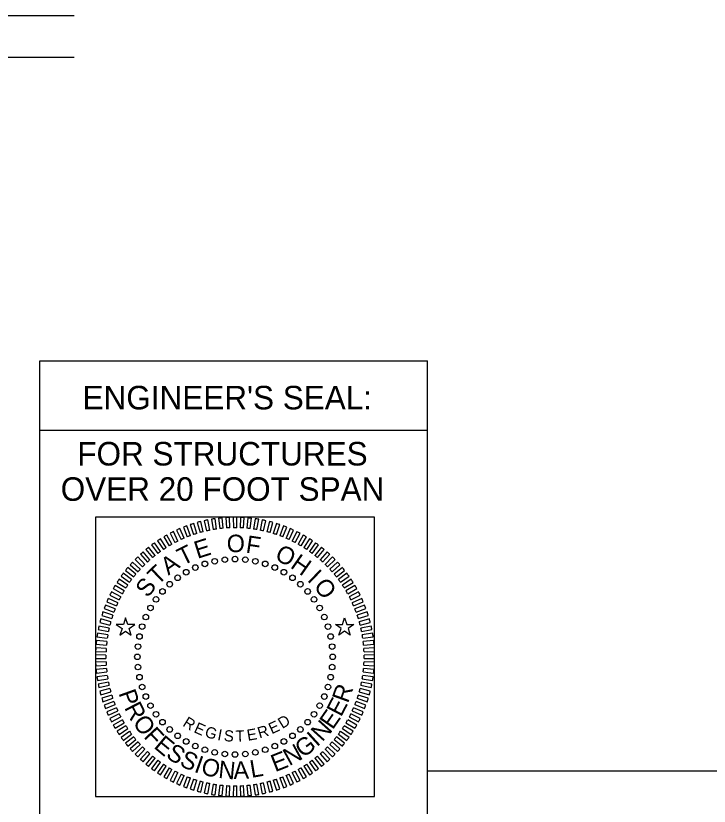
# Model space of a CAD drawing. Extents: x 2080852 to 2433556, y 1080825 to 1306626.
# Drawn here: x 2165094 to 2217967, y 1134021 to 1194273 of the extents above; entities that cross this region are included whole.
import ezdxf

# ---------------------------------------------------------------- set-up
doc = ezdxf.new("R2010")
doc.units = 0
for name, color, linetype in [('Default', 7, 'Continuous'), ('PM_P_Lane_Line', 7, 'Continuous'), ('SC_Scratch1', 7, 'Continuous')]:
    doc.layers.add(name, color=color, linetype=linetype)

msp = doc.modelspace()

# ---------------------------------------------------------------- linework, layer by layer
at = {"layer": 'PM_P_Lane_Line'}
for p, q in [((2169556, 1194273), (2156356, 1194273)), ((2169556, 1191105), (2156356, 1191105)), ((2166916, 1086105), (2166916, 1167965)), ((2166916, 1167965), (2196484, 1167965)), ((2196484, 1086105), (2196484, 1167965)), ((2166916, 1162685), (2196484, 1162685)), ((2178924, 1155648), (2179141, 1154880)), ((2179390, 1154947), (2179193, 1155721)), ((2179464, 1155786), (2179640, 1155007)), ((2179892, 1155061), (2179737, 1155843)), ((2180010, 1155894), (2180146, 1155108)), ((2180400, 1155148), (2180286, 1155938)), ((2180562, 1155974), (2180656, 1155182)), ((2180912, 1155209), (2180839, 1156003)), ((2181116, 1156025), (2181169, 1155229)), ((2181426, 1155242), (2181395, 1156040)), ((2181673, 1156047), (2181684, 1155249)), ((2181941, 1155249), (2181952, 1156047)), ((2182230, 1156040), (2182199, 1155242)), ((2182456, 1155229), (2182508, 1156025)), ((2182786, 1156003), (2182713, 1155209)), ((2182969, 1155182), (2183063, 1155974)), ((2183339, 1155938), (2183225, 1155148)), ((2183479, 1155108), (2183614, 1155894)), ((2183888, 1155843), (2183732, 1155061)), ((2183985, 1155007), (2184161, 1155786)), ((2184431, 1155721), (2184235, 1154947)), ((2184484, 1154880), (2184701, 1155648)), ((2177358, 1155071), (2177692, 1154346)), ((2177927, 1154451), (2177612, 1155184)), ((2177870, 1155290), (2178165, 1154549)), ((2178406, 1154642), (2178130, 1155390)), ((2178392, 1155483), (2178649, 1154728)), ((2178894, 1154807), (2178657, 1155569)), ((2184968, 1155569), (2184731, 1154807)), ((2184976, 1154728), (2185233, 1155483)), ((2185495, 1155390), (2185219, 1154642)), ((2185459, 1154549), (2185755, 1155290)), ((2186013, 1155184), (2185698, 1154451)), ((2185933, 1154346), (2186267, 1155071)), ((2176372, 1154552), (2176780, 1153866)), ((2177003, 1153995), (2176613, 1154691)), ((2176858, 1154824), (2177230, 1154118)), ((2177459, 1154235), (2177106, 1154951)), ((2186518, 1154951), (2186165, 1154235)), ((2186395, 1154118), (2186767, 1154824)), ((2187011, 1154691), (2186621, 1153995)), ((2186845, 1153866), (2187253, 1154552)), ((2175446, 1153933), (2175924, 1153294)), ((2176132, 1153445), (2175671, 1154097)), ((2175901, 1154255), (2176344, 1153591)), ((2176560, 1153732), (2176135, 1154406)), ((2187490, 1154406), (2187064, 1153732)), ((2187280, 1153591), (2187724, 1154255)), ((2187953, 1154097), (2187493, 1153445)), ((2187701, 1153294), (2188179, 1153933)), ((2174590, 1153221), (2175131, 1152635)), ((2175323, 1152807), (2174797, 1153407)), ((2175009, 1153588), (2175519, 1152975)), ((2175719, 1153137), (2175225, 1153764)), ((2188400, 1153764), (2187906, 1153137)), ((2188106, 1152975), (2188616, 1153588)), ((2188828, 1153407), (2188302, 1152807)), ((2188493, 1152635), (2189035, 1153221)), ((2174585, 1152089), (2173999, 1152630)), ((2174191, 1152832), (2174762, 1152275)), ((2174945, 1152458), (2174388, 1153029)), ((2189237, 1153029), (2188680, 1152458)), ((2188862, 1152275), (2189434, 1152832)), ((2189626, 1152630), (2189040, 1152089)), ((2174245, 1151701), (2173632, 1152211)), ((2173813, 1152423), (2174413, 1151897)), ((2189212, 1151897), (2189812, 1152423)), ((2189993, 1152211), (2189379, 1151701)), ((2173123, 1151549), (2173775, 1151088)), ((2173926, 1151297), (2173287, 1151774)), ((2173456, 1151995), (2174083, 1151501)), ((2189542, 1151501), (2190168, 1151995)), ((2190338, 1151774), (2189698, 1151297)), ((2189850, 1151088), (2190502, 1151549)), ((2173354, 1150440), (2172668, 1150848)), ((2172814, 1151085), (2173489, 1150660)), ((2173629, 1150876), (2172965, 1151319)), ((2190659, 1151319), (2189996, 1150876)), ((2190136, 1150660), (2190811, 1151085)), ((2190957, 1150848), (2190271, 1150440)), ((2173102, 1149990), (2172396, 1150362)), ((2172529, 1150607), (2173225, 1150217)), ((2190400, 1150217), (2191096, 1150607)), ((2191229, 1150362), (2190523, 1149990)), ((2172036, 1149608), (2172769, 1149293)), ((2172874, 1149528), (2172150, 1149862)), ((2172269, 1150114), (2172985, 1149761)), ((2190640, 1149761), (2191355, 1150114)), ((2191475, 1149862), (2190750, 1149528)), ((2190855, 1149293), (2191588, 1149608)), ((2171830, 1149090), (2172579, 1148814)), ((2172671, 1149055), (2171930, 1149351)), ((2191695, 1149351), (2190954, 1149055)), ((2191046, 1148814), (2191795, 1149090)), ((2171651, 1148563), (2172413, 1148326)), ((2172493, 1148571), (2171737, 1148828)), ((2191888, 1148828), (2191132, 1148571)), ((2191212, 1148326), (2191974, 1148563)), ((2171500, 1148027), (2172273, 1147830)), ((2172340, 1148079), (2171572, 1148296)), ((2192053, 1148296), (2191285, 1148079)), ((2191352, 1147830), (2192125, 1148027)), ((2172112, 1147074), (2171326, 1147210)), ((2171377, 1147483), (2172159, 1147328)), ((2172213, 1147580), (2171435, 1147756)), ((2192190, 1147756), (2191412, 1147580)), ((2191465, 1147328), (2192248, 1147483)), ((2192299, 1147210), (2191512, 1147074)), ((2172038, 1146565), (2171246, 1146658)), ((2171282, 1146934), (2172072, 1146820)), ((2191553, 1146820), (2192342, 1146934)), ((2192379, 1146658), (2191586, 1146565)), ((2171991, 1146051), (2171195, 1146104)), ((2171217, 1146381), (2172011, 1146308)), ((2191613, 1146308), (2192408, 1146381)), ((2192430, 1146104), (2191633, 1146051)), ((2171971, 1145537), (2171173, 1145547)), ((2171180, 1145825), (2171978, 1145794)), ((2191647, 1145794), (2192444, 1145825)), ((2192452, 1145547), (2191654, 1145537)), ((2171173, 1145268), (2171971, 1145279)), ((2171978, 1145021), (2171180, 1144990)), ((2192444, 1144990), (2191647, 1145021)), ((2191654, 1145279), (2192452, 1145268)), ((2171195, 1144712), (2171991, 1144764)), ((2172011, 1144507), (2171217, 1144434)), ((2171246, 1144157), (2172038, 1144251)), ((2191586, 1144251), (2192379, 1144157)), ((2192408, 1144434), (2191613, 1144507)), ((2191633, 1144764), (2192430, 1144712)), ((2172072, 1143995), (2171282, 1143881)), ((2171326, 1143606), (2172112, 1143741)), ((2191512, 1143741), (2192299, 1143606)), ((2192342, 1143881), (2191553, 1143995)), ((2172159, 1143488), (2171377, 1143332)), ((2171435, 1143059), (2172213, 1143236)), ((2172273, 1142985), (2171500, 1142789)), ((2192125, 1142789), (2191352, 1142985)), ((2191412, 1143236), (2192190, 1143059)), ((2192248, 1143332), (2191465, 1143488)), ((2171572, 1142520), (2172340, 1142736)), ((2172413, 1142489), (2171651, 1142252)), ((2191974, 1142252), (2191212, 1142489)), ((2191285, 1142736), (2192053, 1142520)), ((2171737, 1141988), (2172493, 1142244)), ((2172579, 1142001), (2171830, 1141725)), ((2191795, 1141725), (2191046, 1142001)), ((2191132, 1142244), (2191888, 1141988)), ((2171930, 1141465), (2172671, 1141761)), ((2172769, 1141523), (2172036, 1141208)), ((2172150, 1140953), (2172874, 1141287)), ((2190750, 1141287), (2191475, 1140953)), ((2191588, 1141208), (2190855, 1141523)), ((2190954, 1141761), (2191695, 1141465)), ((2172985, 1141055), (2172269, 1140702)), ((2172396, 1140453), (2173102, 1140825)), ((2173225, 1140599), (2172529, 1140209)), ((2191096, 1140209), (2190400, 1140599)), ((2190523, 1140825), (2191229, 1140453)), ((2191355, 1140702), (2190640, 1141055)), ((2172668, 1139967), (2173354, 1140375)), ((2173489, 1140156), (2172814, 1139730)), ((2190811, 1139730), (2190136, 1140156)), ((2190271, 1140375), (2190957, 1139967)), ((2172965, 1139496), (2173629, 1139940)), ((2173775, 1139727), (2173123, 1139267)), ((2173287, 1139041), (2173926, 1139519)), ((2189698, 1139519), (2190338, 1139041)), ((2190502, 1139267), (2189850, 1139727)), ((2189996, 1139940), (2190659, 1139496)), ((2174083, 1139314), (2173456, 1138820)), ((2173632, 1138604), (2174245, 1139114)), ((2174413, 1138918), (2173813, 1138392)), ((2189812, 1138392), (2189212, 1138918)), ((2189379, 1139114), (2189993, 1138604)), ((2190168, 1138820), (2189542, 1139314)), ((2173999, 1138185), (2174585, 1138727)), ((2174762, 1138540), (2174191, 1137983)), ((2174388, 1137786), (2174945, 1138358)), ((2175131, 1138180), (2174590, 1137594)), ((2189035, 1137594), (2188493, 1138180)), ((2188680, 1138358), (2189237, 1137786)), ((2189434, 1137983), (2188862, 1138540)), ((2189040, 1138727), (2189626, 1138185)), ((2174797, 1137408), (2175323, 1138008)), ((2175519, 1137841), (2175009, 1137227)), ((2175225, 1137052), (2175719, 1137678)), ((2187906, 1137678), (2188400, 1137052)), ((2188616, 1137227), (2188106, 1137841)), ((2188302, 1138008), (2188828, 1137408)), ((2175924, 1137522), (2175446, 1136882)), ((2175671, 1136718), (2176132, 1137370)), ((2176344, 1137224), (2175901, 1136561)), ((2176135, 1136409), (2176560, 1137084)), ((2176780, 1136949), (2176372, 1136263)), ((2187253, 1136263), (2186845, 1136949)), ((2187064, 1137084), (2187490, 1136409)), ((2187724, 1136561), (2187280, 1137224)), ((2187493, 1137370), (2187953, 1136718)), ((2188179, 1136882), (2187701, 1137522)), ((2176613, 1136124), (2177003, 1136820)), ((2177230, 1136697), (2176858, 1135991)), ((2177106, 1135865), (2177459, 1136581)), ((2177692, 1136470), (2177358, 1135745)), ((2177612, 1135632), (2177927, 1136365)), ((2185698, 1136365), (2186013, 1135632)), ((2186267, 1135745), (2185933, 1136470)), ((2186165, 1136581), (2186518, 1135865)), ((2186767, 1135991), (2186395, 1136697)), ((2186621, 1136820), (2187011, 1136124)), ((2196484, 1136706), (2338516, 1136706)), ((2178165, 1136266), (2177870, 1135525)), ((2178130, 1135425), (2178406, 1136174)), ((2178649, 1136088), (2178392, 1135332)), ((2178657, 1135246), (2178894, 1136008)), ((2179141, 1135935), (2178924, 1135167)), ((2179193, 1135095), (2179390, 1135868)), ((2179640, 1135808), (2179464, 1135030)), ((2179737, 1134972), (2179892, 1135755)), ((2183732, 1135755), (2183888, 1134972)), ((2184161, 1135030), (2183985, 1135808)), ((2184235, 1135868), (2184431, 1135095)), ((2184701, 1135167), (2184484, 1135935)), ((2184731, 1136008), (2184968, 1135246)), ((2185233, 1135332), (2184976, 1136088)), ((2185219, 1136174), (2185495, 1135425)), ((2185755, 1135525), (2185459, 1136266)), ((2180146, 1135708), (2180010, 1134921)), ((2180286, 1134878), (2180400, 1135667)), ((2180656, 1135634), (2180562, 1134841)), ((2180839, 1134812), (2180912, 1135607)), ((2181169, 1135587), (2181116, 1134790)), ((2181395, 1134776), (2181426, 1135573)), ((2181684, 1135566), (2181673, 1134768)), ((2181952, 1134768), (2181941, 1135566)), ((2182199, 1135573), (2182230, 1134776)), ((2182508, 1134790), (2182456, 1135587)), ((2182713, 1135607), (2182786, 1134812)), ((2183063, 1134841), (2182969, 1135634)), ((2183225, 1135667), (2183339, 1134878)), ((2183614, 1134921), (2183479, 1135708))]:
    msp.add_line(p, q, dxfattribs=at)
for points in [[(2173897, 1147047), (2173731, 1147558), (2174165, 1147874), (2173628, 1147874), (2173462, 1148385), (2173296, 1147874), (2172758, 1147874), (2173193, 1147558), (2173027, 1147047), (2173462, 1147363), (2173897, 1147047)], [(2189728, 1147047), (2189894, 1147558), (2189459, 1147874), (2189997, 1147874), (2190163, 1148385), (2190329, 1147874), (2190867, 1147874), (2190432, 1147558), (2190598, 1147047), (2190163, 1147363), (2189728, 1147047)]]:
    msp.add_lwpolyline(points, dxfattribs=at)
for centre in [(2179511, 1152491), (2180264, 1152693), (2181034, 1152815), (2181812, 1152856), (2182591, 1152815), (2183361, 1152693), (2184114, 1152491), (2178088, 1151858), (2178783, 1152212), (2184842, 1152212), (2185536, 1151858), (2177434, 1151433), (2186190, 1151433), (2176829, 1150943), (2186796, 1150943), (2176277, 1150391), (2187347, 1150391), (2175787, 1149786), (2187838, 1149786), (2175362, 1149132), (2188263, 1149132), (2175008, 1148437), (2188617, 1148437), (2174729, 1147709), (2188896, 1147709), (2174527, 1146956), (2189098, 1146956), (2174405, 1146186), (2189220, 1146186), (2174364, 1145408), (2189260, 1145408), (2174405, 1144629), (2189220, 1144629), (2174527, 1143859), (2189098, 1143859), (2174729, 1143106), (2188896, 1143106), (2175008, 1142378), (2188617, 1142378), (2175362, 1141684), (2188263, 1141684), (2175787, 1141030), (2187838, 1141030), (2176277, 1140424), (2187347, 1140424), (2176829, 1139873), (2186796, 1139873), (2177434, 1139382), (2186190, 1139382), (2178088, 1138957), (2178783, 1138603), (2184842, 1138603), (2185536, 1138957), (2179511, 1138324), (2180264, 1138122), (2181034, 1138000), (2181812, 1137960), (2182591, 1138000), (2183361, 1138122), (2184114, 1138324)]:
    msp.add_circle(centre, 213, dxfattribs=at)
for radius, start, end in [(10640, 104.25, 105.75), (10640, 101.25, 102.75), (10640, 98.25, 99.75), (10640, 95.25, 96.75), (10640, 92.25, 93.75), (10640, 89.25, 90.75), (10640, 86.25, 87.75), (10640, 83.25, 84.75), (10640, 80.25, 81.75), (10640, 77.25, 78.75), (10640, 74.25, 75.75), (10640, 113.25, 114.75), (10640, 110.25, 111.75), (10640, 107.25, 108.75), (9842, 101.25, 102.75), (9842, 98.25, 99.75), (9842, 95.25, 96.75), (9842, 92.25, 93.75), (9842, 89.25, 90.75), (9842, 86.25, 87.75), (9842, 83.25, 84.75), (9842, 80.25, 81.75), (9842, 77.25, 78.75), (10640, 71.25, 72.75), (10640, 68.25, 69.75), (10640, 65.25, 66.75), (10640, 119.25, 120.75), (10640, 116.25, 117.75), (9842, 113.25, 114.75), (9842, 110.25, 111.75), (9842, 107.25, 108.75), (9842, 104.25, 105.75), (9842, 74.25, 75.75), (9842, 71.25, 72.75), (9842, 68.25, 69.75), (9842, 65.25, 66.75), (10640, 62.25, 63.75), (10640, 59.25, 60.75), (10640, 125.25, 126.75), (10640, 122.25, 123.75), (9842, 119.25, 120.75), (9842, 116.25, 117.75), (9842, 62.25, 63.75), (9842, 59.25, 60.75), (10640, 56.25, 57.75), (10640, 53.25, 54.75), (10640, 131.25, 132.75), (10640, 128.25, 129.75), (9842, 125.25, 126.75), (9842, 122.25, 123.75), (9842, 56.25, 57.75), (9842, 53.25, 54.75), (10640, 50.25, 51.75), (10640, 47.25, 48.75), (10640, 137.25, 138.75), (10640, 134.25, 135.75), (9842, 131.25, 132.75), (9842, 128.25, 129.75), (9842, 50.25, 51.75), (9842, 47.25, 48.75), (10640, 44.25, 45.75), (10640, 41.25, 42.75), (10640, 140.25, 141.75), (9842, 137.25, 138.75), (9842, 134.25, 135.75), (9842, 44.25, 45.75), (9842, 41.25, 42.75), (10640, 38.25, 39.75), (10640, 143.25, 144.75), (9842, 140.25, 141.75), (9842, 38.25, 39.75), (10640, 35.25, 36.75), (10640, 149.25, 150.75), (10640, 146.25, 147.75), (9842, 146.25, 147.75), (9842, 143.25, 144.75), (9842, 35.25, 36.75), (9842, 32.25, 33.75), (10640, 32.25, 33.75), (10640, 29.25, 30.75), (10640, 152.25, 153.75), (9842, 149.25, 150.75), (9842, 29.25, 30.75), (10640, 26.25, 27.75), (10640, 155.25, 156.75), (9842, 152.25, 153.75), (9842, 26.25, 27.75), (10640, 23.25, 24.75), (10640, 158.25, 159.75), (9842, 158.25, 159.75), (9842, 155.25, 156.75), (9842, 23.25, 24.75), (9842, 20.25, 21.75), (10640, 20.25, 21.75), (10640, 161.25, 162.75), (9842, 161.25, 162.75), (9842, 17.25, 18.75), (10640, 17.25, 18.75), (10640, 164.25, 165.75), (9842, 164.25, 165.75), (9842, 14.25, 15.75), (10640, 14.25, 15.75), (10640, 170.25, 171.75), (10640, 167.25, 168.75), (9842, 167.25, 168.75), (9842, 11.25, 12.75), (10640, 11.25, 12.75), (10640, 8.25, 9.75), (10640, 173.25, 174.75), (9842, 170.25, 171.75), (9842, 8.25, 9.75), (10640, 5.25, 6.75), (10640, 176.25, 177.75), (9842, 176.25, 177.75), (9842, 173.25, 174.75), (9842, 5.25, 6.75), (9842, 2.25, 3.75), (10640, 2.25, 3.75), (10640, 179.25, 180.75), (9842, 179.25, 180.75), (9842, 359.25, 0.75), (10640, 359.25, 0.75), (10640, 182.25, 183.75), (9842, 182.25, 183.75), (9842, 356.25, 357.75), (10640, 356.25, 357.75), (10640, 185.25, 186.75), (9842, 185.25, 186.75), (9842, 353.25, 354.75), (10640, 353.25, 354.75), (10640, 188.25, 189.75), (9842, 188.25, 189.75), (9842, 350.25, 351.75), (10640, 350.25, 351.75), (10640, 191.25, 192.75), (9842, 191.25, 192.75), (9842, 194.25, 195.75), (9842, 344.25, 345.75), (9842, 347.25, 348.75), (10640, 347.25, 348.75), (10640, 194.25, 195.75), (9842, 197.25, 198.75), (9842, 341.25, 342.75), (10640, 344.25, 345.75), (10640, 197.25, 198.75), (9842, 200.25, 201.75), (9842, 338.25, 339.75), (10640, 341.25, 342.75), (10640, 200.25, 201.75), (10640, 203.25, 204.75), (9842, 203.25, 204.75), (9842, 335.25, 336.75), (10640, 335.25, 336.75), (10640, 338.25, 339.75), (10640, 206.25, 207.75), (9842, 206.25, 207.75), (9842, 209.25, 210.75), (9842, 329.25, 330.75), (9842, 332.25, 333.75), (10640, 332.25, 333.75), (10640, 209.25, 210.75), (9842, 212.25, 213.75), (9842, 326.25, 327.75), (10640, 329.25, 330.75), (10640, 212.25, 213.75), (9842, 215.25, 216.75), (9842, 323.25, 324.75), (10640, 326.25, 327.75), (10640, 215.25, 216.75), (10640, 218.25, 219.75), (9842, 218.25, 219.75), (9842, 221.25, 222.75), (9842, 317.25, 318.75), (9842, 320.25, 321.75), (10640, 320.25, 321.75), (10640, 323.25, 324.75), (10640, 221.25, 222.75), (9842, 224.25, 225.75), (9842, 227.25, 228.75), (9842, 311.25, 312.75), (9842, 314.25, 315.75), (10640, 317.25, 318.75), (10640, 224.25, 225.75), (10640, 227.25, 228.75), (9842, 230.25, 231.75), (9842, 308.25, 309.75), (10640, 311.25, 312.75), (10640, 314.25, 315.75), (10640, 230.25, 231.75), (9842, 233.25, 234.75), (9842, 236.25, 237.75), (9842, 239.25, 240.75), (9842, 299.25, 300.75), (9842, 302.25, 303.75), (9842, 305.25, 306.75), (10640, 308.25, 309.75), (10640, 233.25, 234.75), (10640, 236.25, 237.75), (9842, 242.25, 243.75), (9842, 245.25, 246.75), (9842, 293.25, 294.75), (9842, 296.25, 297.75), (10640, 302.25, 303.75), (10640, 305.25, 306.75), (10640, 239.25, 240.75), (10640, 242.25, 243.75), (10640, 245.25, 246.75), (9842, 248.25, 249.75), (9842, 251.25, 252.75), (9842, 254.25, 255.75), (9842, 257.25, 258.75), (9842, 281.25, 282.75), (9842, 284.25, 285.75), (9842, 287.25, 288.75), (9842, 290.25, 291.75), (10640, 293.25, 294.75), (10640, 296.25, 297.75), (10640, 299.25, 300.75), (10640, 248.25, 249.75), (10640, 251.25, 252.75), (10640, 254.25, 255.75), (9842, 260.25, 261.75), (9842, 263.25, 264.75), (9842, 266.25, 267.75), (9842, 269.25, 270.75), (9842, 272.25, 273.75), (9842, 275.25, 276.75), (9842, 278.25, 279.75), (10640, 284.25, 285.75), (10640, 287.25, 288.75), (10640, 290.25, 291.75), (10640, 257.25, 258.75), (10640, 260.25, 261.75), (10640, 263.25, 264.75), (10640, 266.25, 267.75), (10640, 269.25, 270.75), (10640, 272.25, 273.75), (10640, 275.25, 276.75), (10640, 278.25, 279.75), (10640, 281.25, 282.75)]:
    msp.add_arc((2181812, 1145408), radius, start, end, dxfattribs=at)
at = {"layer": 'SC_Scratch1'}
msp.add_lwpolyline([(2192453, 1156048), (2171172, 1156048), (2171172, 1134768), (2192453, 1134768)], close=True, dxfattribs=at)

# ---------------------------------------------------------------- texts
at = {"layer": 'Default'}
msp.add_text("ENGINEER'S SEAL:", height=1795.2, dxfattribs=at).set_placement((2170185, 1164269))
at = {"layer": 'PM_P_Lane_Line'}
for s, p in [('FOR STRUCTURES ', (2169784, 1159992)), ('OVER 20 FOOT SPAN', (2168518, 1157299))]:
    msp.add_text(s, height=1795.2, dxfattribs=at).set_placement(p)
for s, height, rotation, p in [('E', 1330, 17.48815, (2178941, 1152870)), ('O', 1330, 360, (2181177, 1153388)), ('F', 1330, 351.25593, (2182583, 1153363)), ('T', 1330, 26.23222, (2177813, 1152333)), ('O', 1330, 333.76778, (2184769, 1152847)), ('H', 1330, 325.0237, (2185960, 1152245)), ('A', 1330, 34.9763, (2176728, 1151590)), ('T', 1330, 43.72037, (2175916, 1150811)), ('I', 1330, 316.27963, (2187264, 1151236)), ('S', 1330, 52.46445, (2175163, 1149851)), ('O', 1330, 307.53555, (2187753, 1150774)), ('R', 1330, 70.05877, (2190415, 1141820)), ('P', 1330, 289.58139, (2172913, 1142646)), ('R', 1330, 297.2357, (2173334, 1141537)), ('E', 1330, 62.45351, (2189895, 1140772)), ('E', 1330, 55.25572, (2189251, 1139796)), ('O', 1330, 305.4844, (2173955, 1140392)), ('R', 851, 328.18241, (2177759, 1140176)), ('E', 851, 24.6051, (2184608, 1139498)), ('D', 851, 31.94957, (2185417, 1139897)), ('N', 1330, 47.93222, (2188461, 1138878)), ('F', 1330, 313.10509, (2174785, 1139291)), ('E', 851, 335.66095, (2178613, 1139682)), ('G', 851, 343.25529, (2179445, 1139332)), ('E', 851, 9.64831, (2182790, 1139003)), ('R', 851, 17.12656, (2183675, 1139179)), ('E', 1330, 320.08209, (2175553, 1138506)), ('I', 851, 349.29866, (2180427, 1139074)), ('S', 851, 355.00964, (2180930, 1138990)), ('T', 851, 2.38957, (2181861, 1138936)), ('I', 1330, 42.49319, (2188053, 1138498)), ('N', 1330, 28.75838, (2185948, 1137057)), ('G', 1330, 36.63019, (2186997, 1137661)), ('S', 1330, 327.42697, (2176466, 1137775)), ('S', 1330, 334.91901, (2177507, 1137143)), ('E', 1330, 21.43495, (2184868, 1136606)), ('I', 1330, 340.38055, (2178624, 1136660)), ('O', 1330, 346.33718, (2179150, 1136474)), ('N', 1330, 354.30419, (2180498, 1136182)), ('A', 1330, 2.20662, (2181705, 1136086)), ('L', 1330, 9.6097, (2183060, 1136176))]:
    msp.add_text(s, height=height, rotation=rotation, dxfattribs=at).set_placement(p)

doc.saveas('drawing.dxf')
